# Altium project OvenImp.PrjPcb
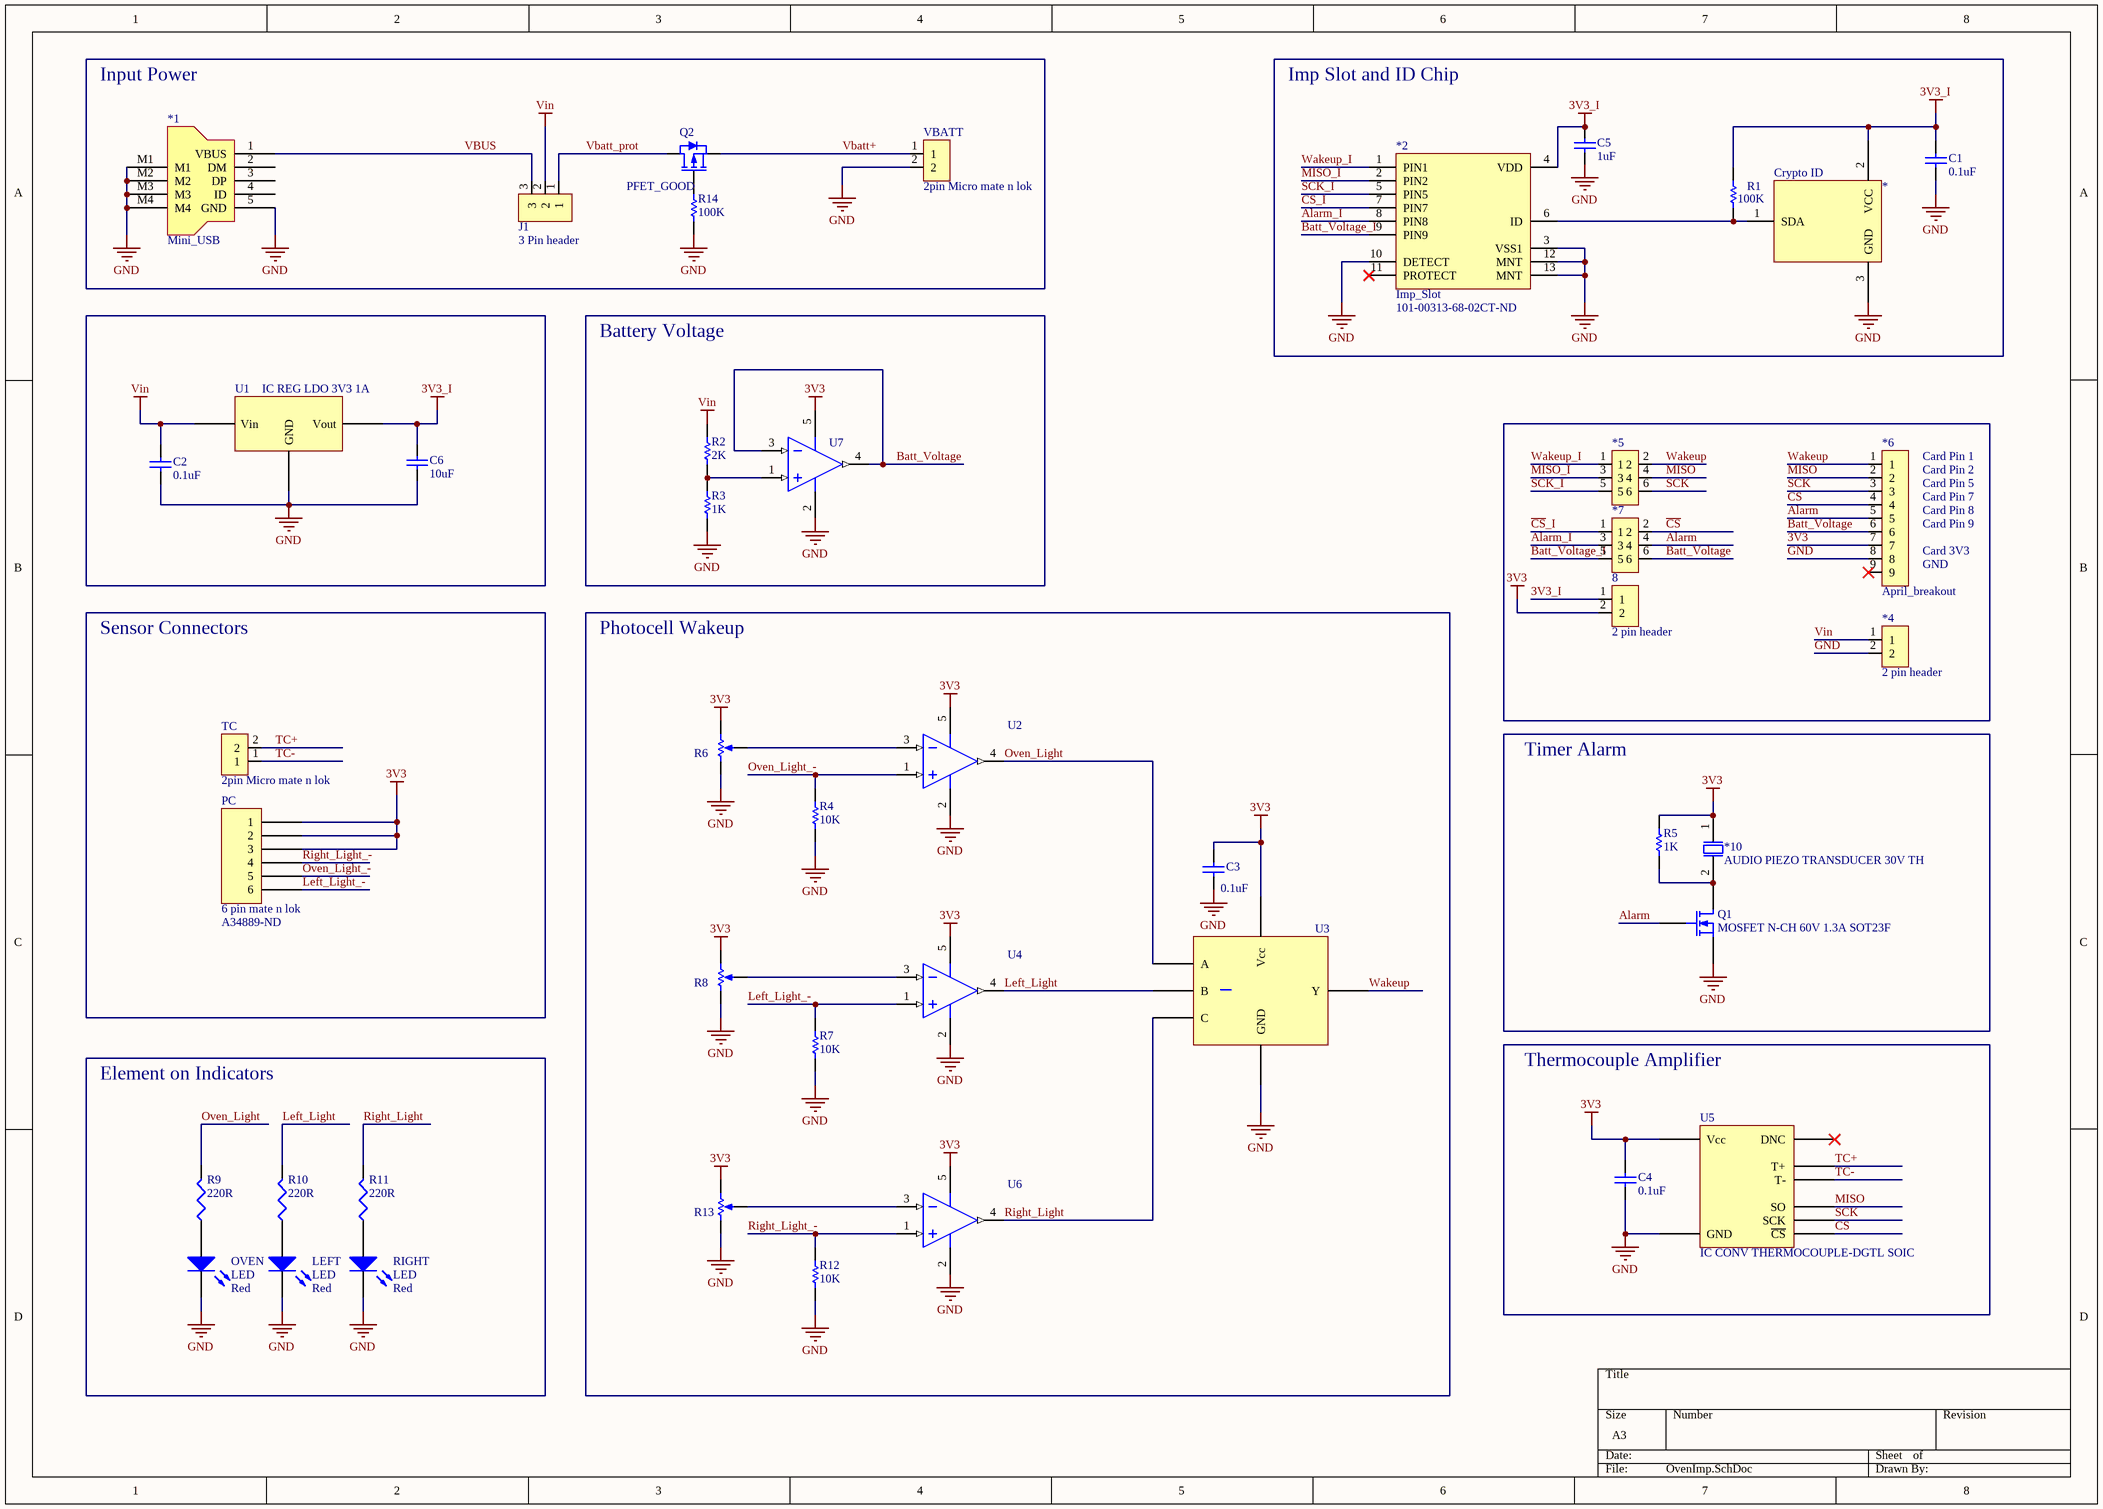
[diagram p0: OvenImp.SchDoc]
1 sheet, 45 parts. Net scope: global (net labels, ports and power ports of the same name join across sheets).
Board file: OvenImp.PcbDoc

## Sheet OvenImp.SchDoc
size A3

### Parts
8  2 pin header  [HDR254P1X2-N]
*  Crypto ID  [SOT23-ATMEL]
*1  Mini_USB  [4ucon20035]
*2  Imp_Slot  Supplier Part Number 1: 101-00313-68-02CT-ND  [IMP_SLOT_COMBO]
*4  2 pin header  [HDR254P1X2-N]
*5  2 pin header_1  [HDR254P2X3-N]  (value not drawn)
*6  April_breakout  [HDR254P1X9-N]
*7  2 pin header_1  [HDR254P2X3-N]  (value not drawn)
*10  AUDIO PIEZO TRANSDUCER 30V TH  [Piezo Buzzer]
C1  0.1uF  [0603_CAPACITOR]
C2  0.1uF  [0603_CAPACITOR]
C3  0.1uF  [0603_CAPACITOR]
C4  0.1uF  [0603_CAPACITOR]
C5  value 1uF  [CAP0603]  (hidden comment: 311-1446-1-ND)
C6  value 10uF  [CAP1206]  (hidden comment: CC1206ZKY5V7BB106)
J1  3 Pin header  [HDR254P1X3-N]
LEFT  LED  Color: Red  [DIOM1608X03N]
OVEN  LED  Color: Red  [DIOM1608X03N]
PC  6 pin mate n lok  Supplier Part Number 1: A34889-ND  [3-794620-6]
Q1  MOSFET N-CH 60V 1.3A SOT23F  [SOT95P240X100-3N]
Q2  PFET_GOOD  [SOT95P240X100-3N]
R1  100K  [0603_Resistor]
R2  2K  [0603_Resistor]
R3  1K  [0603_Resistor]
R4  10K  [0603_Resistor]
R5  1K  [0603_Resistor]
R6  TRIMMER 10K OHM 0.25W SMD  [SMD Trimpot]  (value not drawn)
R7  10K  [0603_Resistor]
R8  TRIMMER 10K OHM 0.25W SMD  [SMD Trimpot]  (value not drawn)
R9  value 220R  [0603_Resistor]  (hidden comment: RC0603FR-07220RL)
R10  value 220R  [0603_Resistor]  (hidden comment: RC0603FR-07220RL)
R11  value 220R  [0603_Resistor]  (hidden comment: RC0603FR-07220RL)
R12  10K  [0603_Resistor]
R13  TRIMMER 10K OHM 0.25W SMD  [SMD Trimpot]  (value not drawn)
R14  100K  [0603_Resistor]
RIGHT  LED  Color: Red  [DIOM1608X03N]
TC  2pin Micro mate n lok  [3-794620-2]
U1  IC REG LDO 3V3 1A  [SOT230P700X180-4N]
U2  IC COMPARATOR VOLT SGL SOT23-5  [SOT95P280X145-5N]  (value not drawn)
U3  IC OR GATE 3 INPUT SOT23-6  [SOT95P280X145-6N]  (value not drawn)
U4  IC COMPARATOR VOLT SGL SOT23-5  [SOT95P280X145-5N]  (value not drawn)
U5  IC CONV THERMOCOUPLE-DGTL SOIC  [SOIC127P600X175-8N]
U6  IC COMPARATOR VOLT SGL SOT23-5  [SOT95P280X145-5N]  (value not drawn)
U7  IC OPAMP GP 1.3MHZ RRO SOT23-5  [SOT95P280X145-5N]  (value not drawn)
VBATT  2pin Micro mate n lok  [3-794620-2]

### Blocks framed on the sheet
Input Power: *1 J1 Q2 R14 VBATT
Imp Slot and ID Chip: * *2 C1 C5 R1
Battery Voltage: R2 R3 U7
Sensor Connectors: PC TC
Photocell Wakeup: C3 R4 R6-R8 R12 R13 U2-U4 U6
Timer Alarm: *10 Q1 R5
Element on Indicators: LEFT OVEN R9-R11 RIGHT
Thermocouple Amplifier: C4 U5

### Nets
3V3: 8.2 *6.7 *10.1(OSC1) C3.2 C4.2 PC.1 PC.2 PC.3 R5.2 R6.3(BOT) R8.3(BOT) R13.3(BOT) U2.5(V+) U3.5(Vcc) U4.5(V+) U5.4(Vcc) U6.5(V+) U7.5(V+)
3V3_I: 8.1 *.2(VCC) *2.4(VDD) C1.2 C5.2 C6.2 R1.2 U1.2(Vout)
GND: *.3(GND) *1.5(GND) *1.M1 *1.M2 *1.M3 *1.M4 *2.3(VSS1) *2.10(DETECT) *2.12(MNT) *2.13(MNT) *4.2 *6.8 C1.1 C2.1 C3.1 C4.1 C5.1 C6.1 LEFT.1(K) OVEN.1(K) Q1.2(S) R3.1 R4.1 R6.1(TOP) R7.1 R8.1(TOP) R12.1 R13.1(TOP) R14.1 RIGHT.1(K) U1.1(GND) U2.2(GND) U3.2(GND) U4.2(GND) U5.1(GND) U6.2(GND) U7.2(GND) VBATT.2
Vin: *4.1 C2.2 J1.2 R2.2 U1.3(Vin)
Alarm: *6.5 *7.4 Q1.1(G)
Alarm_I: *2.8(PIN8) *7.3
Batt_Voltage: *6.6 *7.6 U7.3(IN-) U7.4(OUT)
Batt_Voltage_I: *2.9(PIN9) *7.5
~{CS}: *6.4 *7.2 U5.6(~{CS})
~{CS}_I: *2.7(PIN7) *7.1
Left_Light: R10.2 U3.3(B) U4.4(OUT)
Left_Light_-: PC.6 R7.2 U4.1(IN+)
MISO: *5.4 *6.2 U5.7(SO)
MISO_I: *2.2(PIN2) *5.3
Oven_Light: R9.2 U2.4(OUT) U3.1(A)
Oven_Light_-: PC.5 R4.2 U2.1(IN+)
Right_Light: R11.2 U3.6(C) U6.4(OUT)
Right_Light_-: PC.4 R12.2 U6.1(IN+)
SCK: *5.6 *6.3 U5.5(SCK)
SCK_I: *2.5(PIN5) *5.5
TC+: TC.2 U5.3(T+)
TC-: TC.1 U5.2(T-)
Vbatt+: Q2.2(S) VBATT.1
Vbatt_prot: J1.1 Q2.3(D)
VBUS: *1.1(VBUS) J1.3
Wakeup: *5.2 *6.1 U3.4(Y)
Wakeup_I: *2.1(PIN1) *5.1
Net*10_2: *10.2(OSC2) Q1.3(D) R5.1
Net*_1: *.1(SDA) *2.6(ID) R1.1
NetLEFT_2: LEFT.2(A) R10.1
NetOVEN_2: OVEN.2(A) R9.1
NetQ2_1: Q2.1(G) R14.2
NetR2_1: R2.1 R3.2 U7.1(IN+)
NetR6_2: R6.2(TAP) U2.3(IN-)
NetR8_2: R8.2(TAP) U4.3(IN-)
NetR11_1: R11.1 RIGHT.2(A)
NetR13_2: R13.2(TAP) U6.3(IN-)

Not connected (* = marked no-connect by the designer): *1 2(DM) 3(DP) 4(ID); *2 11(PROTECT)*; *6 9*; U5 8(DNC)*

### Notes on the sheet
- (near *6) Card Pin 1
- (near *6) Card Pin 2
- (near *6) Card Pin 5
- (near *6) Card Pin 7
- (near *6) Card Pin 8
- (near *6) Card Pin 9
- (near *6) Card 3V3
- (near *6) GND

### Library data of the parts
C1-C4 = CAP CER 0.1UF 50V Y5V 0603: 0.1UF CAP 0603
C5 = CC0603KRX7R7BB105: CAP CER 1UF 16V 10% X7R 0603
C6 = CC1206ZKY5V7BB106: CAP CER 10UF 16V Y5V 1206
LEFT OVEN RIGHT = LTST-C193KRKT-5A: LED RED RECT CLEAR 0603; Manufacturer: Lite-On Inc; Millicandela Rating: 26.05mcd; Current - Test: 5mA; Wavelength - Dominant: 631nm; Wavelength - Peak: 639nm; Voltage - Forward (Vf) Typ: 2V; Lens Style/Size: Rectangle, 1.15mm x 0.8mm; Viewing Angle: 130°
R1 R14 = RES SMD 100K OHM 5% 1/10W 0603: 100K OHM Resistor 5%, 1/10W 0603
R2 = RES SMD 2K OHM 5% 1/10W 0603: 2K OHM Resistor 5%, 1/10W 0603
R3 R5 = RES SMD 1K OHM 5% 1/10W 0603: 1K OHM Resistor 5%, 1/10W 0603
R4 R7 R12 = RES SMD 10K OHM 5% 1/10W 0603: 10K OHM Resistor 5%, 1/10W 0603
R9-R11 = RC0603FR-07220RL: RES 220 OHM 1/10W 1% 0603 SMD
U1 = IC REG LDO 3V3 1A: 3.3V LDO SOT223
U2 U4 U6 = IC COMPARATOR VOLT SGL SOT23-5: Comparator SOT23
U3 = IC OR GATE 3 INPUT SOT23-6: OR Gate 3 Input
U5 = IC CONV THERMOCOUPLE-DGTL SOIC: Thermocouple to Digital Converter
U7 = IC OPAMP GP 1.3MHZ RRO SOT23-5: OPAMP SOT23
